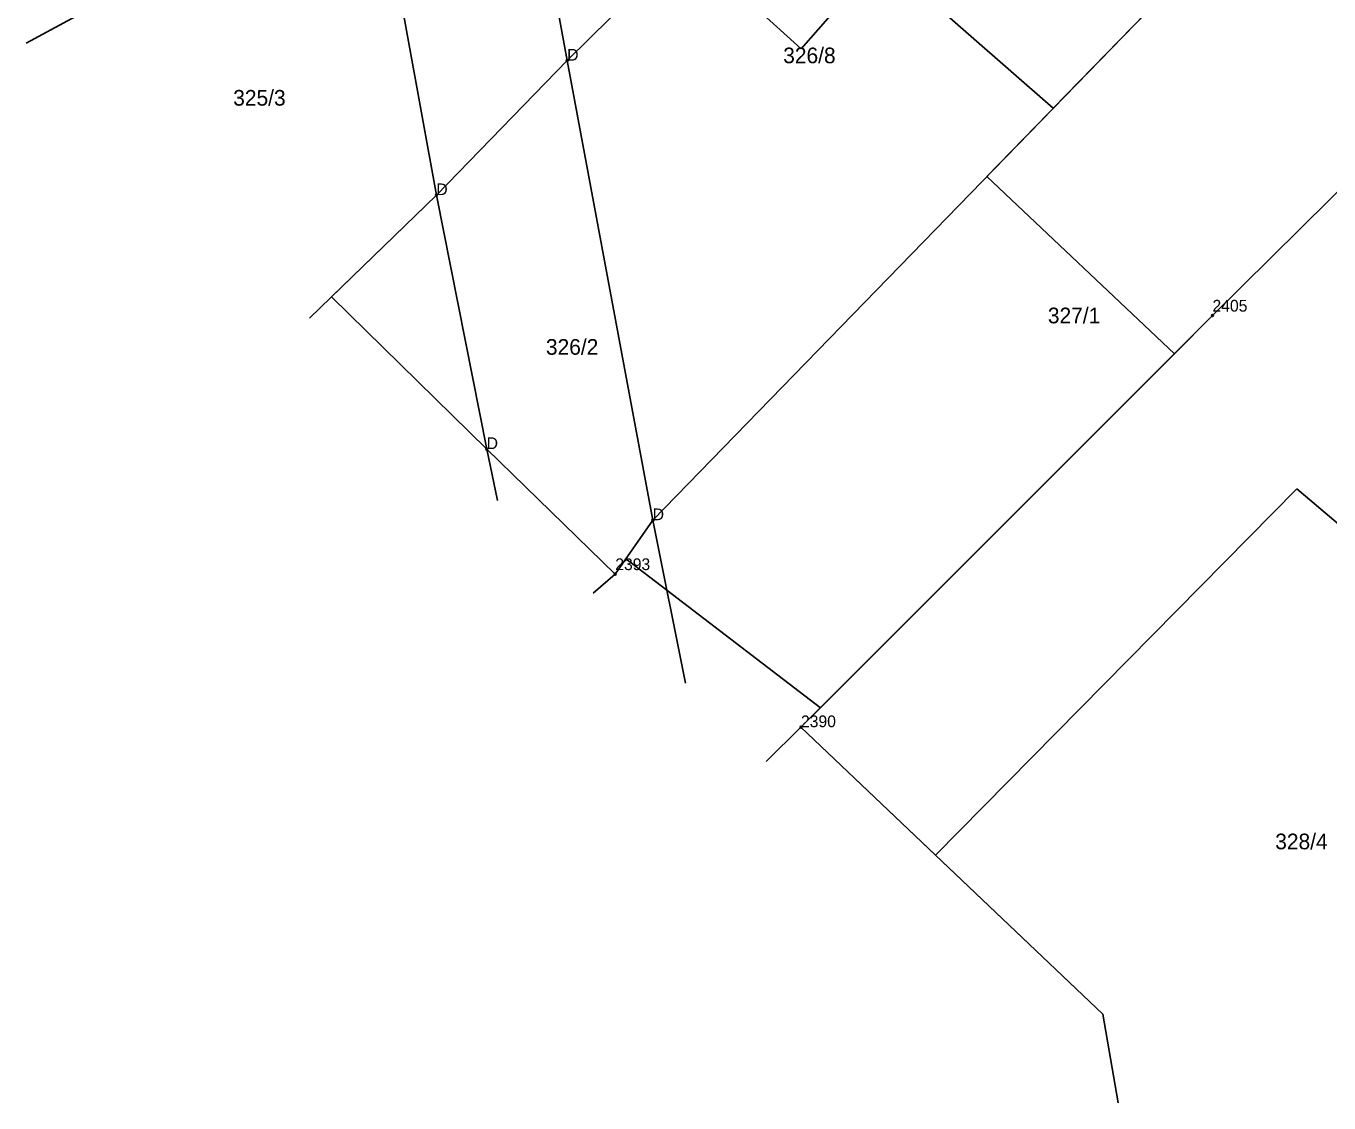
# Model space of a CAD drawing. Extents: x 7467189 to 7469366, y 5491487 to 5492734.
# Drawn here: x 7467684.8 to 7467809.6, y 5491710.7 to 5491813.8 of the extents above; entities that cross this region are included whole.
import ezdxf

# ---------------------------------------------------------------- set-up
doc = ezdxf.new("R2010")
doc.units = 0
for name, color, linetype in [('203-punkt graniczny', 7, 'Continuous'), ('203-punkt graniczny-Atr103', 7, 'Continuous'), ('211-numer działki ewidencyjnej', 7, 'Continuous'), ('217-kontur klasyfikacyjny', 7, 'Continuous'), ('218-kontur użytku gruntowego', 7, 'Continuous'), ('219-działka ewidencyjna', 7, 'Continuous')]:
    doc.layers.add(name, color=color, linetype=linetype)

# ---------------------------------------------------------------- blocks, each defined once
blk = doc.blocks.new('203')
blk.add_circle((0, 0), 0.09)

msp = doc.modelspace()

# ---------------------------------------------------------------- linework, layer by layer
at = {"layer": '217-kontur klasyfikacyjny'}
for points in [[(7467742.92, 5491816.72), (7467736.66, 5491810.51)], [(7467776.84, 5491799.42), (7467793.32, 5491816.37)], [(7467736.66, 5491810.51), (7467724.13, 5491797.63)], [(7467818.09, 5491805.55), (7467798.44, 5491786.1)], [(7467794.79, 5491782.45), (7467776.84, 5491799.42)], [(7467724.13, 5491797.63), (7467714.08, 5491787.89)], [(7467714.08, 5491787.89), (7467728.95, 5491773.32)], [(7467798.44, 5491786.1), (7467794.79, 5491782.45)], [(7467794.79, 5491782.45), (7467778.93, 5491766.59)], [(7467728.95, 5491773.32), (7467741.26, 5491761.35)], [(7467771.91, 5491734.45), (7467806.51, 5491769.51)], [(7467806.51, 5491769.51), (7467814.02, 5491763.17)], [(7467778.93, 5491766.59), (7467760.91, 5491748.56)], [(7467741.26, 5491761.35), (7467742.28, 5491762.82)], [(7467742.28, 5491762.82), (7467746.2, 5491759.82)], [(7467746.2, 5491759.82), (7467760.91, 5491748.56)], [(7467760.91, 5491748.56), (7467759.04, 5491746.69)], [(7467759.04, 5491746.69), (7467771.91, 5491734.45)], [(7467771.91, 5491734.45), (7467787.95, 5491719.21)], [(7467787.95, 5491719.21), (7467789.42, 5491710.71)]]:
    msp.add_lwpolyline(points, dxfattribs=at)
at = {"layer": '218-kontur użytku gruntowego'}
for points in [[(7467747.72, 5491821.91), (7467759.05, 5491811.64)], [(7467759.05, 5491811.64), (7467766.73, 5491820.38)], [(7467766.73, 5491820.38), (7467783.2, 5491805.97)], [(7467736.66, 5491810.51), (7467742.92, 5491816.72)], [(7467783.2, 5491805.97), (7467793.32, 5491816.37)], [(7467724.13, 5491797.63), (7467736.66, 5491810.51)], [(7467818.09, 5491805.55), (7467798.44, 5491786.1)], [(7467714.08, 5491787.89), (7467724.13, 5491797.63)], [(7467728.95, 5491773.32), (7467714.08, 5491787.89)], [(7467798.44, 5491786.1), (7467778.93, 5491766.59)], [(7467741.26, 5491761.35), (7467728.95, 5491773.32)], [(7467778.93, 5491766.59), (7467766.69, 5491754.34)], [(7467742.28, 5491762.82), (7467741.26, 5491761.35)], [(7467746.2, 5491759.82), (7467742.28, 5491762.82)], [(7467760.91, 5491748.56), (7467746.2, 5491759.82)], [(7467766.69, 5491754.34), (7467760.91, 5491748.56)], [(7467760.91, 5491748.56), (7467759.04, 5491746.69)], [(7467759.04, 5491746.69), (7467787.95, 5491719.21)], [(7467787.95, 5491719.21), (7467789.42, 5491710.71)]]:
    msp.add_lwpolyline(points, dxfattribs=at)
at = {"layer": '219-działka ewidencyjna'}
for points in [[(7467736.66, 5491810.51), (7467732.36, 5491833.99)], [(7467718.35, 5491829.56), (7467724.13, 5491797.63)], [(7467684.85, 5491812.19), (7467702.36, 5491821.65)], [(7467736.66, 5491810.51), (7467742.92, 5491816.72)], [(7467744.85, 5491766.51), (7467793.32, 5491816.37)], [(7467724.13, 5491797.63), (7467736.66, 5491810.51)], [(7467736.66, 5491810.51), (7467744.85, 5491766.51)], [(7467818.09, 5491805.55), (7467798.44, 5491786.1)], [(7467711.98, 5491785.86), (7467724.13, 5491797.63)], [(7467724.13, 5491797.63), (7467728.95, 5491773.32)], [(7467759.04, 5491746.69), (7467798.44, 5491786.1)], [(7467728.95, 5491773.32), (7467729.98, 5491768.39)], [(7467744.85, 5491766.51), (7467741.26, 5491761.35)], [(7467744.85, 5491766.51), (7467747.99, 5491750.91)], [(7467739.14, 5491759.51), (7467741.26, 5491761.35)], [(7467755.71, 5491743.42), (7467759.04, 5491746.69)]]:
    msp.add_lwpolyline(points, dxfattribs=at)

# ---------------------------------------------------------------- block references
at = {"layer": '203-punkt graniczny'}
for p in [(7467736.66, 5491810.51), (7467724.13, 5491797.63), (7467798.44, 5491786.1), (7467728.95, 5491773.32), (7467744.85, 5491766.51), (7467741.26, 5491761.35), (7467759.04, 5491746.69)]:
    msp.add_blockref('203', p, dxfattribs=at)

# ---------------------------------------------------------------- texts
at = {"layer": '203-punkt graniczny-Atr103'}
for s, height, p in [('D', 1.12, (7467736.66, 5491810.51)), ('D', 1.12, (7467724.13, 5491797.63)), ('2405', 1.125, (7467798.44, 5491786.48)), ('D', 1.12, (7467728.95, 5491773.32)), ('D', 1.12, (7467744.85, 5491766.51)), ('2393', 1.125, (7467741.26, 5491761.73)), ('2390', 1.125, (7467759.04, 5491746.69))]:
    msp.add_text(s, height=height, dxfattribs=at).set_placement(p)
at = {"layer": '211-numer działki ewidencyjnej'}
for s, p in [('326/8', (7467757.34, 5491810.26)), ('325/3', (7467704.68, 5491806.2)), ('327/1', (7467782.68, 5491785.36)), ('326/2', (7467734.62, 5491782.35)), ('328/4', (7467804.45, 5491735))]:
    msp.add_text(s, height=1.5, dxfattribs=at).set_placement(p)

doc.saveas('drawing.dxf')
